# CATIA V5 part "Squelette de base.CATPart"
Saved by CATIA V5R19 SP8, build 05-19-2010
Part number: Squelette de base
Bounding box of the stored display mesh (mm): x -58 to 89, y -51 to 51, z 0 to 176
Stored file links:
  G:\EU_thinkMotion\CFAO_2010\MMS_groupe1\MMS_groupe1\A reprendre\OK\glenerrant\glenerrant\glenerrant\Squelette de base.CATPart
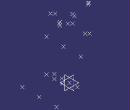
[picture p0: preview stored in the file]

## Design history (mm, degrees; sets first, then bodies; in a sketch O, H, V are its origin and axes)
Set1
  Point1: (0, 0, 0)
  Point2: (45, 0, 32)
  Point3: (89, 0, 8)
  Point4: (45, 0, 45)
  Point5: (17, 0, 101)
  Point6: (-9, 0, 147)
  Point7: (5, 0, 154)
  Point8: (5, 51, 154)
  Point9: (-9, 51, 147)
  Point10: (17, 51, 101)
  Point11: (17, -51, 101)
  Point12: (-9, -51, 147)
  Point13: (5, -51, 154)
  Point14: (89, -51, 8)
  Point15: (89, 51, 8)
  Point16: (45, 23, 32)
  Point17: (45, -23, 32)
  Point18: (0, -23, 0)
  Point19: (0, 23, 0)
  Point20: (28, 0, 161)
  Point21: (31, 0, 166)
  Point22: (28, 0, 170)
  Point23: (-56, 0, 176)
  Point24: (-58, 0, 175)
  Point25: (-56, 0, 172)
  Point26: (-10, 0, 170)
  Point27: (-15, 0, 163)
Body1 (main body)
